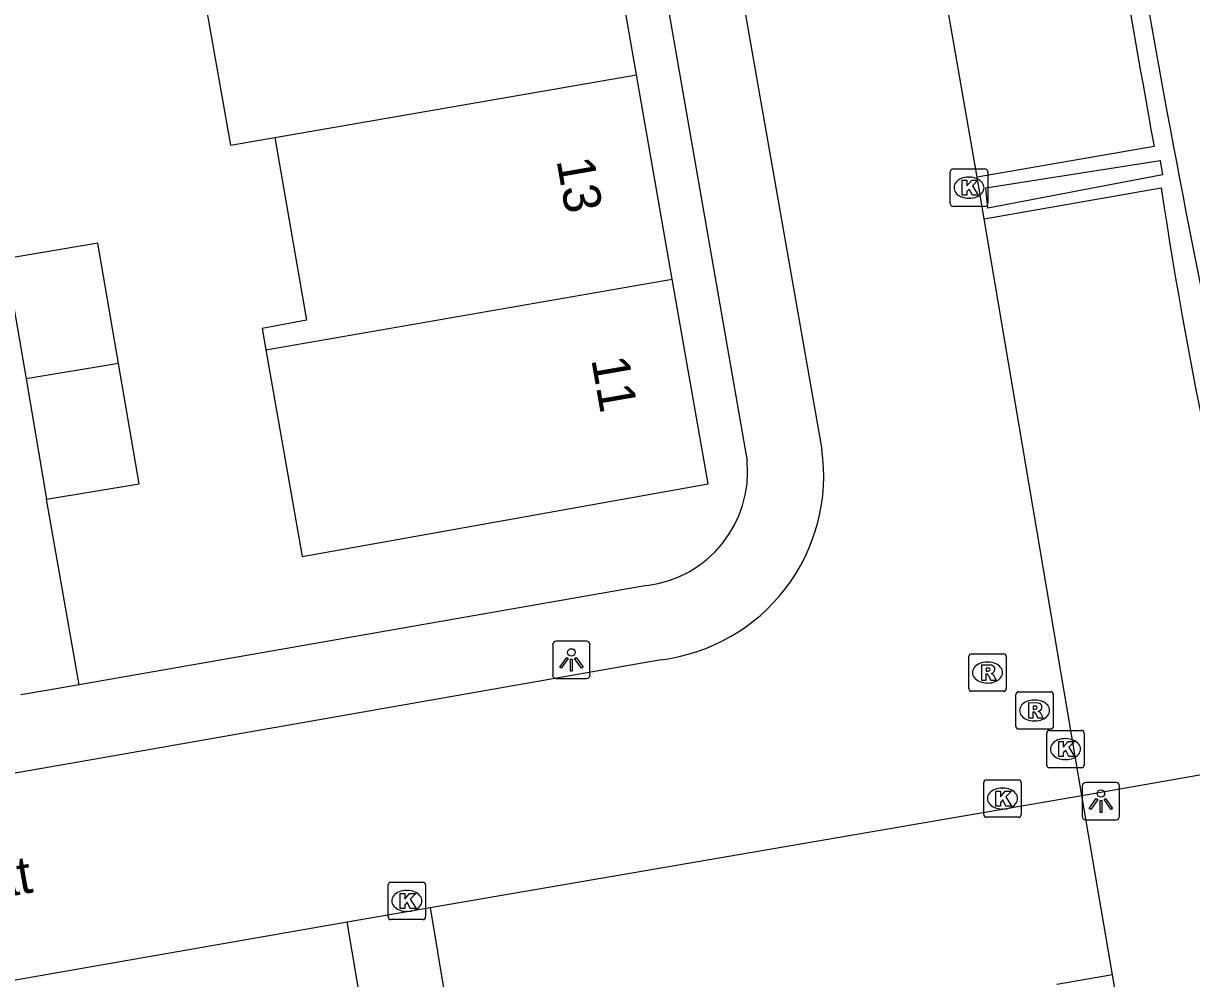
# Model space of a CAD drawing. Extents: x 160158 to 160921, y 381517 to 382041.
# Drawn here: x 160466.28 to 160497.47, y 381586.1 to 381611.61 of the extents above; entities that cross this region are included whole.
import ezdxf

# ---------------------------------------------------------------- set-up
doc = ezdxf.new("R2010")
doc.units = 0
for name, color, linetype in [('IMGEO_Haag', 7, 'Continuous'), ('IMGEO_Kolk', 7, 'Continuous'), ('IMGEO_Lichtpunt', 7, 'Continuous'), ('IMGEO_Openbare_ruimte_label', 7, 'Continuous'), ('IMGEO_Pand', 7, 'Continuous'), ('IMGEO_Pand_nummerreeks', 7, 'Continuous'), ('IMGEO_Parkeervlak_open', 7, 'Continuous'), ('IMGEO_Rijbaan_lokaal_open', 7, 'Continuous'), ('IMGEO_Rioolput', 7, 'Continuous'), ('IMGEO_Voetpad_open', 7, 'Continuous')]:
    doc.layers.add(name, color=color, linetype=linetype)

msp = doc.modelspace()

# ---------------------------------------------------------------- linework, layer by layer
at = {"layer": 'IMGEO_Haag'}
msp.add_lwpolyline([(160492.028, 381606.677), (160491.975, 381607.223), (160496.627, 381607.953), (160496.689, 381607.565), (160492.028, 381606.677)], dxfattribs=at)
at = {"layer": 'IMGEO_Kolk'}
for p, q in [((160491.025, 381606.799), (160491.025, 381607.651)), ((160491.1, 381607.725), (160491.952, 381607.725)), ((160491.513, 381607.505), (160491.538, 381607.505)), ((160492.026, 381607.651), (160492.026, 381606.799)), ((160491.536, 381606.945), (160491.511, 381606.945)), ((160491.952, 381606.725), (160491.1, 381606.725)), ((160493.599, 381591.808), (160493.599, 381592.66)), ((160493.674, 381592.734), (160494.526, 381592.734)), ((160494.087, 381592.514), (160494.112, 381592.514)), ((160494.6, 381592.66), (160494.6, 381591.808)), ((160494.11, 381591.954), (160494.085, 381591.954)), ((160494.526, 381591.734), (160493.674, 381591.734)), ((160491.918, 381590.487), (160491.918, 381591.339)), ((160491.993, 381591.413), (160492.845, 381591.413)), ((160492.919, 381591.339), (160492.919, 381590.487)), ((160492.406, 381591.193), (160492.431, 381591.193)), ((160492.429, 381590.633), (160492.404, 381590.633)), ((160492.845, 381590.413), (160491.993, 381590.413)), ((160476.019, 381587.754), (160476.019, 381588.606)), ((160476.094, 381588.68), (160476.946, 381588.68)), ((160476.507, 381588.46), (160476.532, 381588.46)), ((160477.02, 381588.606), (160477.02, 381587.754)), ((160476.53, 381587.9), (160476.505, 381587.9)), ((160476.946, 381587.68), (160476.094, 381587.68))]:
    msp.add_line(p, q, dxfattribs=at)
for points in [[(160491.025, 381606.799), (160491.025, 381607.651)], [(160491.1, 381607.725), (160491.952, 381607.725)], [(160491.346, 381607.425), (160491.469, 381607.425), (160491.469, 381607.274), (160491.599, 381607.425), (160491.763, 381607.425), (160491.617, 381607.274), (160491.77, 381607.025), (160491.618, 381607.025), (160491.533, 381607.189), (160491.469, 381607.122), (160491.469, 381607.025), (160491.346, 381607.025), (160491.346, 381607.425)], [(160492.026, 381607.651), (160492.026, 381606.799)], [(160491.952, 381606.725), (160491.1, 381606.725)], [(160493.599, 381591.808), (160493.599, 381592.66)], [(160493.674, 381592.734), (160494.526, 381592.734)], [(160494.6, 381592.66), (160494.6, 381591.808)], [(160493.92, 381592.434), (160494.043, 381592.434), (160494.043, 381592.283), (160494.173, 381592.434), (160494.337, 381592.434), (160494.191, 381592.283), (160494.344, 381592.034), (160494.192, 381592.034), (160494.107, 381592.198), (160494.043, 381592.131), (160494.043, 381592.034), (160493.92, 381592.034), (160493.92, 381592.434)], [(160494.526, 381591.734), (160493.674, 381591.734)], [(160491.918, 381590.487), (160491.918, 381591.339)], [(160491.993, 381591.413), (160492.845, 381591.413)], [(160492.919, 381591.339), (160492.919, 381590.487)], [(160492.239, 381591.113), (160492.362, 381591.113), (160492.362, 381590.962), (160492.492, 381591.113), (160492.656, 381591.113), (160492.51, 381590.962), (160492.663, 381590.713), (160492.511, 381590.713), (160492.426, 381590.877), (160492.362, 381590.81), (160492.362, 381590.713), (160492.239, 381590.713), (160492.239, 381591.113)], [(160492.845, 381590.413), (160491.993, 381590.413)], [(160476.019, 381587.754), (160476.019, 381588.606)], [(160476.094, 381588.68), (160476.946, 381588.68)], [(160477.02, 381588.606), (160477.02, 381587.754)], [(160476.34, 381588.38), (160476.463, 381588.38), (160476.463, 381588.229), (160476.593, 381588.38), (160476.757, 381588.38), (160476.611, 381588.229), (160476.764, 381587.98), (160476.612, 381587.98), (160476.527, 381588.144), (160476.463, 381588.077), (160476.463, 381587.98), (160476.34, 381587.98), (160476.34, 381588.38)], [(160476.946, 381587.68), (160476.094, 381587.68)]]:
    msp.add_lwpolyline(points, dxfattribs=at)
for centre, start, end in [((160491.102, 381607.649), 91.552, 178.448), ((160491.102, 381607.649), 91.552, 178.448), ((160491.95, 381607.649), 1.552, 88.448), ((160491.95, 381607.649), 1.552, 88.448), ((160491.102, 381606.801), 181.552, 268.448), ((160491.102, 381606.801), 181.552, 268.448), ((160491.95, 381606.801), 271.552, 358.448), ((160491.95, 381606.801), 271.552, 358.448), ((160493.676, 381592.658), 91.552, 178.448), ((160493.676, 381592.658), 91.552, 178.448), ((160494.524, 381592.658), 1.552, 88.448), ((160494.524, 381592.658), 1.552, 88.448), ((160493.676, 381591.81), 181.552, 268.448), ((160493.676, 381591.81), 181.552, 268.448), ((160494.524, 381591.81), 271.552, 358.448), ((160494.524, 381591.81), 271.552, 358.448), ((160491.995, 381591.337), 91.552, 178.448), ((160491.995, 381591.337), 91.552, 178.448), ((160492.843, 381591.337), 1.552, 88.448), ((160492.843, 381591.337), 1.552, 88.448), ((160491.995, 381590.489), 181.552, 268.448), ((160491.995, 381590.489), 181.552, 268.448), ((160492.843, 381590.489), 271.552, 358.448), ((160492.843, 381590.489), 271.552, 358.448), ((160476.096, 381588.604), 91.552, 178.448), ((160476.096, 381588.604), 91.552, 178.448), ((160476.944, 381588.604), 1.552, 88.448), ((160476.944, 381588.604), 1.552, 88.448), ((160476.096, 381587.756), 181.552, 268.448), ((160476.096, 381587.756), 181.552, 268.448), ((160476.944, 381587.756), 271.552, 358.448), ((160476.944, 381587.756), 271.552, 358.448)]:
    msp.add_arc(centre, 0.0765, start, end, dxfattribs=at)
for centre, major_axis, ratio, start_param, end_param in [((160491.512, 381607.225), (-0.387, 0.002), 0.722429, 4.712389, 7.853982), ((160491.537, 381607.225), (-0.39, 0.002), 0.717154, 1.570796, 4.712389), ((160494.086, 381592.234), (-0.387, 0.002), 0.722429, 4.712389, 7.853982), ((160494.111, 381592.234), (-0.39, 0.002), 0.717154, 1.570796, 4.712389), ((160492.405, 381590.913), (-0.387, 0.002), 0.722429, 4.712389, 7.853982), ((160492.43, 381590.913), (-0.39, 0.002), 0.717154, 1.570796, 4.712389), ((160476.506, 381588.18), (-0.387, 0.002), 0.722429, 4.712389, 7.853982), ((160476.531, 381588.18), (-0.39, 0.002), 0.717154, 1.570796, 4.712389)]:
    msp.add_ellipse(centre, major_axis=major_axis, ratio=ratio, start_param=start_param, end_param=end_param, dxfattribs=at)
at = {"layer": 'IMGEO_Lichtpunt'}
for p, q in [((160480.412, 381595.018), (160480.412, 381594.211)), ((160480.412, 381595.018), (160480.412, 381594.211)), ((160481.314, 381595.113), (160480.506, 381595.113)), ((160481.314, 381595.113), (160480.506, 381595.113)), ((160481.408, 381594.211), (160481.408, 381595.018)), ((160481.408, 381594.211), (160481.408, 381595.018)), ((160480.506, 381594.117), (160481.314, 381594.117)), ((160480.506, 381594.117), (160481.314, 381594.117)), ((160494.548, 381591.249), (160494.548, 381590.442)), ((160494.548, 381591.249), (160494.548, 381590.442)), ((160495.45, 381591.344), (160494.642, 381591.344)), ((160495.45, 381591.344), (160494.642, 381591.344)), ((160495.544, 381590.442), (160495.544, 381591.249)), ((160495.544, 381590.442), (160495.544, 381591.249)), ((160494.642, 381590.348), (160495.45, 381590.348)), ((160494.642, 381590.348), (160495.45, 381590.348))]:
    msp.add_line(p, q, dxfattribs=at)
for points in [[(160480.786, 381594.682), (160480.825, 381594.654), (160480.637, 381594.392), (160480.599, 381594.419), (160480.786, 381594.682)], [(160480.888, 381594.634), (160480.935, 381594.634), (160480.935, 381594.312), (160480.888, 381594.312), (160480.888, 381594.634)], [(160480.998, 381594.654), (160481.036, 381594.681), (160481.223, 381594.419), (160481.184, 381594.391), (160480.998, 381594.654)], [(160494.922, 381590.913), (160494.961, 381590.885), (160494.773, 381590.623), (160494.735, 381590.65), (160494.922, 381590.913)], [(160495.134, 381590.885), (160495.172, 381590.912), (160495.359, 381590.65), (160495.32, 381590.622), (160495.134, 381590.885)], [(160495.024, 381590.865), (160495.071, 381590.865), (160495.071, 381590.543), (160495.024, 381590.543), (160495.024, 381590.865)]]:
    msp.add_lwpolyline(points, dxfattribs=at)
for centre in [(160480.911, 381594.816), (160495.047, 381591.047)]:
    msp.add_circle(centre, 0.0994, dxfattribs=at)
for centre, start, end in [((160480.506, 381595.018), 90, 180), ((160480.506, 381595.018), 90, 180), ((160481.314, 381595.018), 0, 90), ((160481.314, 381595.018), 0, 90), ((160480.506, 381594.211), 180, 270), ((160480.506, 381594.211), 180, 270), ((160481.314, 381594.211), 270, 0), ((160481.314, 381594.211), 270, 360), ((160494.642, 381591.249), 90, 180), ((160494.642, 381591.249), 90, 180), ((160495.45, 381591.249), 0, 90), ((160495.45, 381591.249), 0, 90), ((160494.642, 381590.442), 180, 270), ((160494.642, 381590.442), 180, 270), ((160495.45, 381590.442), 270, 0), ((160495.45, 381590.442), 270, 360)]:
    msp.add_arc(centre, 0.0946, start, end, dxfattribs=at)
at = {"layer": 'IMGEO_Pand'}
for points in [[(160482.651, 381610.241), (160481.697, 381615.705)], [(160471.977, 381614.31), (160470.796, 381614.101), (160471.812, 381608.364), (160472.996, 381608.567)], [(160472.996, 381608.567), (160482.651, 381610.241)], [(160483.605, 381604.778), (160482.651, 381610.241)], [(160472.996, 381608.567), (160473.837, 381603.686), (160472.658, 381603.461), (160472.757, 381602.897)], [(160468.821, 381602.529), (160468.271, 381605.739), (160465.806, 381605.327)], [(160465.806, 381605.327), (160466.355, 381602.117)], [(160472.757, 381602.897), (160483.605, 381604.778)], [(160472.757, 381602.897), (160473.729, 381597.378), (160484.559, 381599.314), (160483.605, 381604.778)], [(160468.821, 381602.529), (160466.355, 381602.117)], [(160466.903, 381598.91), (160469.371, 381599.318), (160468.821, 381602.529)], [(160466.355, 381602.117), (160466.903, 381598.91)]]:
    msp.add_lwpolyline(points, dxfattribs=at)
at = {"layer": 'IMGEO_Parkeervlak_open'}
for points in [[(160496.465, 381608.327), (160491.745, 381607.509)], [(160491.933, 381606.393), (160496.656, 381607.224)], [(160494.54, 381590.991), (160499.964, 381591.951)], [(160495.352, 381586.205), (160494.54, 381590.991)], [(160477.14, 381588.004), (160477.934, 381583.215)], [(160475.736, 381582.816), (160474.925, 381587.623)]]:
    msp.add_lwpolyline(points, dxfattribs=at)
for centre, radius, start, end in [((160982.712, 381696.345), 494.149, 188.71093, 190.26024), ((160614.079, 381624.662), 118.711, 188.44705, 195.99496)]:
    msp.add_arc(centre, radius, start, end, dxfattribs=at)
at = {"layer": 'IMGEO_Rijbaan_lokaal_open'}
for points in [[(160491.745, 381607.509), (160489.449, 381620.675)], [(160484.484, 381617.982), (160487.598, 381600.238)], [(160491.933, 381606.393), (160491.745, 381607.509)], [(160494.54, 381590.991), (160491.933, 381606.393)], [(160483.304, 381594.619), (160468.514, 381592.021), (160442.874, 381587.548)], [(160477.14, 381588.004), (160494.54, 381590.991)], [(160474.925, 381587.623), (160477.14, 381588.004)], [(160460.872, 381585.165), (160474.925, 381587.623)]]:
    msp.add_lwpolyline(points, dxfattribs=at)
msp.add_arc((160482.695, 381599.534), 4.953, 277.0585, 8.1678, dxfattribs=at)
at = {"layer": 'IMGEO_Rioolput'}
for p, q in [((160491.519, 381593.852), (160491.519, 381594.704)), ((160491.594, 381594.778), (160492.446, 381594.778)), ((160492.52, 381594.704), (160492.52, 381593.852)), ((160492.007, 381594.558), (160492.032, 381594.558)), ((160492.446, 381593.778), (160491.594, 381593.778)), ((160492.03, 381593.998), (160492.005, 381593.998)), ((160492.85, 381593.765), (160493.702, 381593.765)), ((160492.775, 381592.839), (160492.775, 381593.691)), ((160493.263, 381593.545), (160493.288, 381593.545)), ((160493.776, 381593.691), (160493.776, 381592.839)), ((160493.702, 381592.765), (160492.85, 381592.765)), ((160493.286, 381592.985), (160493.261, 381592.985))]:
    msp.add_line(p, q, dxfattribs=at)
for points in [[(160491.519, 381593.852), (160491.519, 381594.704)], [(160491.594, 381594.778), (160492.446, 381594.778)], [(160492.52, 381594.704), (160492.52, 381593.852)], [(160492.108, 381594.476), (160491.856, 381594.478), (160491.856, 381594.078)], [(160492.034, 381594.397), (160491.98, 381594.397), (160491.98, 381594.316)], [(160491.856, 381594.078), (160491.98, 381594.078), (160491.98, 381594.24), (160491.991, 381594.24)], [(160491.98, 381594.316), (160492.032, 381594.316)], [(160492.038, 381594.211), (160492.109, 381594.078), (160492.249, 381594.078), (160492.184, 381594.204)], [(160492.446, 381593.778), (160491.594, 381593.778)], [(160492.85, 381593.765), (160493.702, 381593.765)], [(160492.775, 381592.839), (160492.775, 381593.691)], [(160493.364, 381593.463), (160493.112, 381593.465), (160493.112, 381593.065)], [(160493.29, 381593.384), (160493.236, 381593.384), (160493.236, 381593.303)], [(160493.776, 381593.691), (160493.776, 381592.839)], [(160493.112, 381593.065), (160493.236, 381593.065), (160493.236, 381593.227), (160493.247, 381593.227)], [(160493.236, 381593.303), (160493.288, 381593.303)], [(160493.294, 381593.198), (160493.365, 381593.065), (160493.505, 381593.065), (160493.44, 381593.191)], [(160493.702, 381592.765), (160492.85, 381592.765)]]:
    msp.add_lwpolyline(points, dxfattribs=at)
for centre, radius, start, end in [((160491.596, 381594.702), 0.0765, 91.552, 178.448), ((160491.596, 381594.702), 0.0765, 91.552, 178.448), ((160492.444, 381594.702), 0.0765, 1.552, 88.448), ((160492.444, 381594.702), 0.0765, 1.552, 88.448), ((160492.016, 381594.505), 0.19, 274.7715, 282.9687), ((160492.04, 381594.301), 0.0964, 77.0061, 93.1865), ((160492.054, 381594.358), 0.0378, 276.6634, 79.6772), ((160492.107, 381594.366), 0.109, 350.3612, 89.416), ((160492.105, 381594.366), 0.112, 277.5842, 350.9817), ((160491.99, 381594.187), 0.0533, 26.0293, 88.6989), ((160492.089, 381594.151), 0.108, 29.5134, 73.7905), ((160491.596, 381593.854), 0.0765, 181.552, 268.448), ((160491.596, 381593.854), 0.0765, 181.552, 268.448), ((160492.444, 381593.854), 0.0765, 271.552, 358.448), ((160492.444, 381593.854), 0.0765, 271.552, 358.448), ((160492.852, 381593.689), 0.0765, 91.552, 178.448), ((160492.852, 381593.689), 0.0765, 91.552, 178.448), ((160493.7, 381593.689), 0.0765, 1.552, 88.448), ((160493.7, 381593.689), 0.0765, 1.552, 88.448), ((160493.296, 381593.288), 0.0964, 77.0061, 93.1865), ((160493.31, 381593.345), 0.0378, 276.6634, 79.6772), ((160493.363, 381593.353), 0.109, 350.3612, 89.416), ((160493.246, 381593.174), 0.0533, 26.0293, 88.6989), ((160493.272, 381593.492), 0.19, 274.7715, 282.9687), ((160493.361, 381593.353), 0.112, 277.5842, 350.9817), ((160493.345, 381593.138), 0.108, 29.5134, 73.7905), ((160492.852, 381592.841), 0.0765, 181.552, 268.448), ((160492.852, 381592.841), 0.0765, 181.552, 268.448), ((160493.7, 381592.841), 0.0765, 271.552, 358.448), ((160493.7, 381592.841), 0.0765, 271.552, 358.448)]:
    msp.add_arc(centre, radius, start, end, dxfattribs=at)
for centre, major_axis, ratio, start_param, end_param in [((160492.006, 381594.278), (-0.387, 0.002), 0.722429, 4.712389, 7.853982), ((160492.031, 381594.278), (-0.39, 0.002), 0.717154, 1.570796, 4.712389), ((160493.262, 381593.265), (-0.387, 0.002), 0.722429, 4.712389, 7.853982), ((160493.287, 381593.265), (-0.39, 0.002), 0.717154, 1.570796, 4.712389)]:
    msp.add_ellipse(centre, major_axis=major_axis, ratio=ratio, start_param=start_param, end_param=end_param, dxfattribs=at)
at = {"layer": 'IMGEO_Voetpad_open'}
for points in [[(160482.021, 381620.491), (160485.603, 381599.926)], [(160467.769, 381593.951), (160466.903, 381598.91)], [(160482.924, 381596.599), (160467.769, 381593.951)], [(160467.769, 381593.951), (160466.899, 381593.799), (160466.211, 381593.679)], [(160495.352, 381586.205), (160493.871, 381585.951)], [(160495.493, 381585.429), (160495.352, 381586.205)]]:
    msp.add_lwpolyline(points, dxfattribs=at)
for centre, radius, start, end in [((160831.721, 381671.168), 340.586, 188.18081, 193.07206), ((160482.555, 381599.638), 3.061, 276.9208, 5.3951)]:
    msp.add_arc(centre, radius, start, end, dxfattribs=at)

# ---------------------------------------------------------------- texts
at = {"layer": 'IMGEO_Openbare_ruimte_label'}
msp.add_text('Diabellistraat', height=1, rotation=9.9051, dxfattribs=at).set_placement((160458.956, 381587.085))
at = {"layer": 'IMGEO_Pand_nummerreeks'}
for s, p in [('13', (160480.512, 381607.958)), ('11', (160481.44, 381602.642))]:
    msp.add_text(s, height=1, rotation=279.9062, dxfattribs=at).set_placement(p)

doc.saveas('drawing.dxf')
